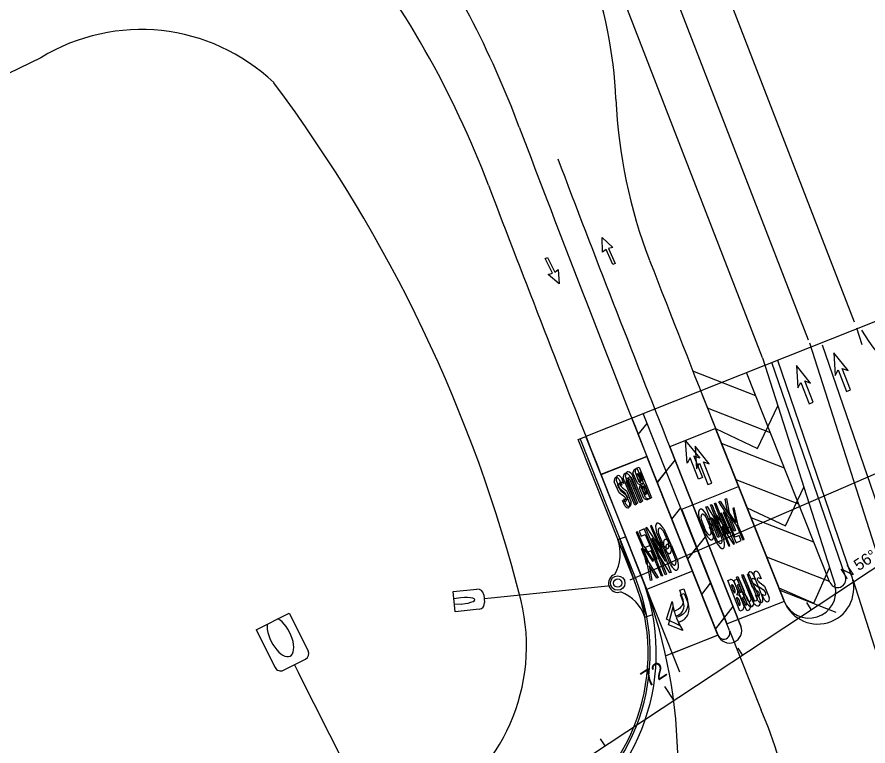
# Model space of a CAD drawing. Extents: x 468143 to 491361, y 1438528 to 1468730.
# Drawn here: x 489927.9 to 490134.6, y 1467030.2 to 1467207.3 of the extents above; entities that cross this region are included whole.
import ezdxf

# ---------------------------------------------------------------- set-up
doc = ezdxf.new("R2010")
doc.units = 0
doc.layers.add('Default', color=7, linetype='Continuous')
doc.layers.add('Xreference_dp', color=7, linetype='Continuous')

# ---------------------------------------------------------------- blocks, each defined once
blk = doc.blocks.new('POINT_DISPLAY')
at = {"layer": 'Default'}
blk.add_line((0, 0), (0, 0), dxfattribs=at)
blk = doc.blocks.new('InltCurb2_35')
at = {"layer": 'Default'}
for p, q in [((-10, 2), (-10, 0)), ((-10, 1.5), (10, 1.5)), ((10, 2), (10, 0))]:
    blk.add_line(p, q, dxfattribs=at)
for radius in [1.75, 1]:
    blk.add_circle((0, 5.5), radius, dxfattribs=at)
for centre, radius, start, end in [((0, 5.5), 2.25, 0, 180), ((-9.85, 12), 10, 269.1432, 319.4677), ((9.85, 12), 10, 220.5323, 270.8568)]:
    blk.add_arc(centre, radius, start, end, dxfattribs=at)
for p in [(-1.6, 6.2), (-1.22, 6.76), (-0.66, 7.12), (0, 7.75), (0, 7.25), (0, 7.25), (0.7, 7.1), (1.26, 6.72), (-1.75, 5.5), (-1.75, 5.5), (-1.62, 4.84), (-1.26, 4.28), (0, 5.5), (0, 5.5), (1.22, 4.24), (1.6, 4.8), (1.62, 6.16), (1.75, 5.5), (1.75, 5.5), (-0.7, 3.9), (0, 3.75), (0, 3.75), (0.66, 3.88), (0, 0), (0, 0)]:
    blk.add_blockref('POINT_DISPLAY', p, dxfattribs=at)
blk = doc.blocks.new('MESC18RCP4S')
at = {"layer": 'Default'}
for p, q in [((-0.96, 2.29), (0.96, 2.29)), ((0, 2.29), (0, 3.97)), ((-2.46, -5.03), (-2.46, 0.79)), ((2.46, 0.79), (2.46, -5.03)), ((-0.75, -3.28), (-0.71, -5.03)), ((0.75, -3.28), (0.7, -5.03)), ((2.46, -5.03), (-2.46, -5.03))]:
    blk.add_line(p, q, dxfattribs=at)
for centre, start, end in [((-0.96, 0.79), 90, 180), ((0.96, 0.79), 0, 90)]:
    blk.add_arc(centre, 1.5, start, end, dxfattribs=at)
blk.add_ellipse((0, -3), major_axis=(0, 3), ratio=0.25, start_param=4.617261, end_param=7.949056, dxfattribs=at)
for p in [(0, 3.97), (0, 2.29), (0, 0), (0, 0), (0, -5.03)]:
    blk.add_blockref('POINT_DISPLAY', p, dxfattribs=at)
blk = doc.blocks.new('MESC60RCP2S')
at = {"layer": 'Default'}
for p, q in [((0, 2.34), (0, 4.55)), ((3, 2.34), (-3, 2.34)), ((-4.5, -9.45), (-4.5, 0.84)), ((4.5, -9.45), (4.5, 0.84)), ((4.5, -9.45), (-4.5, -9.45))]:
    blk.add_line(p, q, dxfattribs=at)
for centre, start, end in [((-3, 0.84), 90, 180), ((3, 0.84), 0, 90)]:
    blk.add_arc(centre, 1.5, start, end, dxfattribs=at)
blk.add_ellipse((0, -5.22), major_axis=(0, -5.22), ratio=0.478691, start_param=0.629157, end_param=5.654028, dxfattribs=at)
for p in [(0, 4.55), (0, 2.34), (0, 0), (0, 0), (0, -9.45)]:
    blk.add_blockref('POINT_DISPLAY', p, dxfattribs=at)
blk = doc.blocks.new('DARightTurn')
at = {"layer": 'Default'}
for points in [[(2, 2.17), (0, 2.17), (0, 3.17), (2.67, 3.17)], [(5.67, -3.17), (2, -0.5), (4.33, -0.83), (4.33, -0.17)], [(6, -0.17), (6, -0.83), (8.25, -0.5), (5.67, -3.17)]]:
    blk.add_lwpolyline(points, dxfattribs=at)
for centre, radius in [((2, -0.17), 2.33), ((2.67, -0.17), 3.33)]:
    blk.add_arc(centre, radius, 360, 90, dxfattribs=at)
blk = doc.blocks.new('ONLY_5')
at = {"layer": 'Default'}
for p, q in [((1.94, 3.96), (6.06, 3.96)), ((5.6, 3.63), (2.4, 3.63)), ((2.4, 2.29), (5.6, 2.29)), ((6.06, 1.96), (1.94, 1.96))]:
    blk.add_line(p, q, dxfattribs=at)
for points in [[(0, -0.12), (0, 0.21), (5, 1.13), (0, 1.13), (0, 1.46), (8, 1.46), (8, 1.13), (2.9, 0.21), (8, 0.21), (8, -0.12), (0, -0.12)], [(1.33, -2.12), (0, -2.12), (0, -0.79), (8, -0.79), (8, -1.12), (1.33, -1.12), (1.33, -2.12)], [(8, -3.96), (3.67, -3.12), (0, -3.12), (0, -2.79), (3.67, -2.79), (8, -1.96), (8, -2.3), (4.57, -2.96), (8, -3.62), (8, -3.96)]]:
    blk.add_lwpolyline(points, dxfattribs=at)
for major_axis, ratio, start_param, end_param in [((4, 0), 0.291667, 2.111896, 4.171289), ((2.67, 0), 0.3125, 2.214297, 4.068888), ((2.67, 0), 0.3125, 5.35589, 7.210481), ((4, 0), 0.291667, 5.253489, 7.312882)]:
    blk.add_ellipse((4, 2.96), major_axis=major_axis, ratio=ratio, start_param=start_param, end_param=end_param, dxfattribs=at)
blk = doc.blocks.new('BUS_6')
at = {"layer": 'Default'}
for p, q in [((0, 2.46), (0, 3.17)), ((0, 3.17), (8, 3.17)), ((3.33, 2.83), (1.33, 2.83)), ((1.33, 2.83), (1.33, 2.58)), ((3.33, 2.58), (3.33, 2.83)), ((6.67, 2.83), (4.67, 2.83)), ((4.67, 2.83), (4.67, 2.58)), ((6.67, 2.58), (6.67, 2.83)), ((8, 3.17), (8, 2.46)), ((3.38, 1.83), (0.62, 1.83)), ((0.97, 0.86), (8, 0.86)), ((8, 0.5), (2, 0.5)), ((7.38, 1.83), (4.62, 1.83)), ((8, 0.86), (8, 0.5)), ((0.8, -1.83), (2.26, -1.83)), ((8, -0.83), (0.89, -0.83)), ((2, -0.5), (8, -0.5)), ((3.08, -2.5), (4.23, -1.83)), ((4.23, -1.83), (7.2, -1.83)), ((8, -0.5), (8, -0.83)), ((3.77, -3.17), (0.8, -3.17)), ((4.93, -2.5), (3.77, -3.17)), ((7.2, -3.17), (5.74, -3.17))]:
    blk.add_line(p, q, dxfattribs=at)
for centre, major_axis, ratio, start_param, end_param in [((2, 2.83), (-2.08, 0), 0.64, 0.283794, 0.848062), ((2.33, 2.83), (-1.17, 0), 0.428571, 0.5411, 2.600493), ((2, 2.83), (-2.08, 0), 0.64, 2.293531, 2.857799), ((6, 2.83), (2.08, 0), 0.64, 3.425387, 3.989655), ((5.67, 2.83), (1.17, 0), 0.428571, 3.682692, 5.742086), ((6, 2.83), (2.08, 0), 0.64, 5.435123, 5.999391), ((2, 0), (2, 0), 0.5, 2.110653, 4.126703), ((2, 0), (0.667, 0), 0.75, 1.570796, 4.712389), ((2, -2.5), (-2, 0), 0.416667, 5.35589, 7.210481), ((2.67, -2.17), (-0.877, -0.48), 0.5, 4.914869, 8.056461), ((6, -2.5), (2, 0), 0.416667, 5.35589, 7.210481), ((5.33, -2.83), (-0.869, -0.495), 0.5, 1.760499, 4.902092)]:
    blk.add_ellipse(centre, major_axis=major_axis, ratio=ratio, start_param=start_param, end_param=end_param, dxfattribs=at)
blk = doc.blocks.new('DAThru_1')
at = {"layer": 'Default'}
blk.add_lwpolyline([(4.58, -1.67), (5.58, -0.5), (0, -0.5), (0, 0.5), (5.58, 0.5), (4.58, 1.67), (9.83, 0), (4.58, -1.67)], dxfattribs=at)
blk = doc.blocks.new('DAMerge')
at = {"layer": 'Default'}
blk.add_lwpolyline([(0.71, -4.09), (4.66, -0.15), (4.77, -1.68), (7.31, 3.21), (2.42, 0.68), (3.95, 0.56), (0, -3.39), (0.71, -4.09)], dxfattribs=at)
blk = doc.blocks.new('DALeftTurn_4')
at = {"layer": 'Default'}
for points in [[(5.67, 3.17), (2, 0.5), (4.33, 0.83), (4.33, 0.17)], [(6, 0.17), (6, 0.83), (8.25, 0.5), (5.67, 3.17)], [(2, -2.17), (0, -2.17), (0, -3.17), (2.67, -3.17)]]:
    blk.add_lwpolyline(points, dxfattribs=at)
for centre, radius in [((2, 0.17), 2.33), ((2.67, 0.17), 3.33)]:
    blk.add_arc(centre, radius, 270, 0, dxfattribs=at)
blk = doc.blocks.new('BikeONLY')
at = {"layer": 'Default'}
for p, q in [((0.97, 1.83), (3.03, 1.83)), ((2.8, 1.67), (1.2, 1.67)), ((3.03, 0.83), (0.97, 0.83)), ((1.2, 1), (2.8, 1))]:
    blk.add_line(p, q, dxfattribs=at)
for points in [[(0, -0.17), (4, -0.17), (4, 0), (1.45, 0), (4, 0.46), (4, 0.62), (0, 0.62), (0, 0.46), (2.5, 0.46), (0, 0), (0, -0.17)], [(0, -1.04), (0.67, -1.04), (0.67, -0.54), (4, -0.54), (4, -0.37), (0, -0.37), (0, -1.04)], [(4, -1.83), (4, -1.66), (2.28, -1.33), (4, -1), (4, -0.83), (1.83, -1.25), (0, -1.25), (0, -1.42), (1.83, -1.42), (4, -1.83)]]:
    blk.add_lwpolyline(points, dxfattribs=at)
for major_axis, ratio, start_param, end_param in [((2, 0), 0.291667, 2.111896, 4.171289), ((1.33, 0), 0.3125, 2.214297, 4.068888), ((1.33, 0), 0.3125, 5.35589, 7.210481), ((2, 0), 0.291667, 5.253489, 7.312882)]:
    blk.add_ellipse((2, 1.33), major_axis=major_axis, ratio=ratio, start_param=start_param, end_param=end_param, dxfattribs=at)
blk = doc.blocks.new('BUS')
at = {"layer": 'Default'}
for p, q in [((0, 2.46), (0, 3.17)), ((0, 3.17), (8, 3.17)), ((3.33, 2.83), (1.33, 2.83)), ((1.33, 2.83), (1.33, 2.58)), ((3.33, 2.58), (3.33, 2.83)), ((6.67, 2.83), (4.67, 2.83)), ((4.67, 2.83), (4.67, 2.58)), ((6.67, 2.58), (6.67, 2.83)), ((8, 3.17), (8, 2.46)), ((3.38, 1.83), (0.62, 1.83)), ((0.97, 0.86), (8, 0.86)), ((8, 0.5), (2, 0.5)), ((7.38, 1.83), (4.62, 1.83)), ((8, 0.86), (8, 0.5)), ((0.8, -1.83), (2.26, -1.83)), ((8, -0.83), (0.89, -0.83)), ((2, -0.5), (8, -0.5)), ((3.08, -2.5), (4.23, -1.83)), ((4.23, -1.83), (7.2, -1.83)), ((8, -0.5), (8, -0.83)), ((3.77, -3.17), (0.8, -3.17)), ((4.93, -2.5), (3.77, -3.17)), ((7.2, -3.17), (5.74, -3.17))]:
    blk.add_line(p, q, dxfattribs=at)
for centre, major_axis, ratio, start_param, end_param in [((2, 2.83), (-2.08, 0), 0.64, 0.283794, 0.848062), ((2.33, 2.83), (-1.17, 0), 0.428571, 0.5411, 2.600493), ((2, 2.83), (-2.08, 0), 0.64, 2.293531, 2.857799), ((6, 2.83), (2.08, 0), 0.64, 3.425387, 3.989655), ((5.67, 2.83), (1.17, 0), 0.428571, 3.682692, 5.742086), ((6, 2.83), (2.08, 0), 0.64, 5.435123, 5.999391), ((2, 0), (2, 0), 0.5, 2.110653, 4.126703), ((2, 0), (0.667, 0), 0.75, 1.570796, 4.712389), ((2, -2.5), (-2, 0), 0.416667, 5.35589, 7.210481), ((2.67, -2.17), (-0.877, -0.48), 0.5, 4.914869, 8.056461), ((6, -2.5), (2, 0), 0.416667, 5.35589, 7.210481), ((5.33, -2.83), (-0.869, -0.495), 0.5, 1.760499, 4.902092)]:
    blk.add_ellipse(centre, major_axis=major_axis, ratio=ratio, start_param=start_param, end_param=end_param, dxfattribs=at)

msp = doc.modelspace()

# ---------------------------------------------------------------- linework, layer by layer
at = {"layer": 'Xreference_dp'}
for p, q in [((490131.32, 1467133.11), (490088.77, 1467243.04)), ((490131.32, 1467133.11), (490088.77, 1467243.04)), ((490120.13, 1467128.78), (490077.58, 1467238.71)), ((490120.13, 1467128.78), (490077.58, 1467238.71)), ((490108.94, 1467124.45), (490066.39, 1467234.38)), ((490108.94, 1467124.45), (490066.39, 1467234.38)), ((489933.74, 1467197.39), (489863.69, 1467163.48)), ((489933.74, 1467197.39), (489863.69, 1467163.48)), ((490051.34, 1467017.44), (490235.32, 1467139.02)), ((490136.39, 1467133.34), (490066.06, 1467105.41)), ((490131.8, 1467131.76), (490133.08, 1467127.75)), ((490131.8, 1467131.76), (490133.08, 1467127.75)), ((490120.37, 1467128.1), (490138, 1467072.93)), ((490120.37, 1467128.1), (490138, 1467072.93)), ((490141.39, 1467075.55), (490123.54, 1467127.57)), ((490108.94, 1467124.45), (490126.57, 1467069.27)), ((490108.94, 1467124.45), (490126.57, 1467069.27)), ((490129.09, 1467071.33), (490111.24, 1467123.35)), ((490130.51, 1467071.81), (490112.66, 1467123.84)), ((490107.33, 1467115.29), (490092.06, 1467121.24)), ((490125.34, 1467069.94), (490105.1, 1467120.91)), ((490114.19, 1467065.51), (490093.95, 1467116.48)), ((490172.03, 1467111.76), (490076.72, 1467070.5)), ((490100.95, 1467058.21), (490080.01, 1467110.94)), ((490110.9, 1467106.29), (490095.63, 1467112.24)), ((490098.16, 1467057.1), (490077.22, 1467109.84)), ((490078.81, 1467105.82), (490080.96, 1467108.54)), ((490114.25, 1467065.34), (490097.59, 1467107.29)), ((490114.25, 1467065.34), (490097.59, 1467107.29)), ((490064.21, 1467104.67), (490066.06, 1467105.41)), ((490077.8, 1467070.45), (490064.21, 1467104.67)), ((490078.26, 1467070.64), (490064.67, 1467104.85)), ((490079.65, 1467071.19), (490066.06, 1467105.41)), ((490079.56, 1467071.42), (490066.06, 1467105.41)), ((490103.73, 1467059.31), (490086.43, 1467102.86)), ((490103.73, 1467059.31), (490086.43, 1467102.86)), ((490114.31, 1467097.71), (490099.04, 1467103.66)), ((490098.15, 1467057.1), (490080.89, 1467100.55)), ((490098.15, 1467057.1), (490080.89, 1467100.55)), ((490083.42, 1467094.18), (490087.72, 1467099.61)), ((490083.42, 1467094.18), (490087.72, 1467099.61)), ((490083.44, 1467094.18), (490085.59, 1467096.89)), ((490117.81, 1467088.9), (490102.54, 1467094.85)), ((490086.95, 1467085.32), (490089.1, 1467088.04)), ((490121.46, 1467079.7), (490106.19, 1467085.65)), ((490090.81, 1467075.59), (490095.1, 1467081.02)), ((490090.81, 1467075.59), (490095.1, 1467081.02)), ((490090.82, 1467075.59), (490092.97, 1467078.31)), ((490125.27, 1467070.11), (490110, 1467076.06)), ((490094.22, 1467067.02), (490096.37, 1467069.73)), ((490130.87, 1467070.64), (490142.34, 1467034.75)), ((490043.04, 1467066.17), (490072.16, 1467069.19)), ((490126.85, 1467062.65), (490113.22, 1467067.96)), ((490097.55, 1467058.61), (490101.85, 1467064.05)), ((490097.55, 1467058.61), (490101.85, 1467064.05)), ((490120.81, 1467063.35), (490119.71, 1467065.02)), ((490097.56, 1467058.61), (490099.71, 1467061.33)), ((490098.16, 1467057.1), (490085.49, 1467052.07)), ((490098.15, 1467057.1), (490087, 1467052.67)), ((490098.15, 1467057.1), (490087, 1467052.67)), ((490100.95, 1467058.21), (490108.61, 1467038.92)), ((490104.13, 1467052.32), (490103.02, 1467053.99)), ((490021.16, 1466998.87), (489996.32, 1467047.97)), ((490087.44, 1467041.3), (490085.24, 1467044.63)), ((490070.76, 1467030.27), (490069.65, 1467031.94))]:
    msp.add_line(p, q, dxfattribs=at)
for points in [[(490073.21, 1467147.43), (490072.64, 1467147.18), (490071.03, 1467150.77), (490070.14, 1467150.16), (490070.06, 1467153.69), (490072.64, 1467151.29), (490071.6, 1467151.02)], [(490073.21, 1467147.43), (490072.64, 1467147.18), (490071.03, 1467150.77), (490070.14, 1467150.16), (490070.06, 1467153.69), (490072.64, 1467151.29), (490071.6, 1467151.02)], [(490056.21, 1467148.59), (490056.77, 1467148.87), (490058.51, 1467145.33), (490059.38, 1467145.97), (490059.58, 1467142.44), (490056.91, 1467144.76), (490057.95, 1467145.06)], [(490056.21, 1467148.59), (490056.77, 1467148.87), (490058.51, 1467145.33), (490059.38, 1467145.97), (490059.58, 1467142.44), (490056.91, 1467144.76), (490057.95, 1467145.06)], [(490091.98, 1467072.67), (490080.83, 1467068.24), (490069.75, 1467096.12), (490080.9, 1467100.55)], [(490089.34, 1467087.72), (490103.16, 1467093.21), (490114.24, 1467065.33), (490100.42, 1467059.84)]]:
    msp.add_lwpolyline(points, close=True, dxfattribs=at)
for points in [[(490097.59, 1467107.29), (490107.78, 1467102.47), (490112.66, 1467112.79)], [(490097.59, 1467107.29), (490107.78, 1467102.47), (490112.66, 1467112.79)], [(490114.25, 1467065.34), (490097.59, 1467107.29), (490086.43, 1467102.86), (490103.73, 1467059.31)], [(490114.25, 1467065.34), (490097.59, 1467107.29), (490086.43, 1467102.86), (490103.73, 1467059.31)], [(490069.74, 1467096.12), (490080.89, 1467100.55)], [(490098.15, 1467057.1), (490080.89, 1467100.55), (490069.74, 1467096.12), (490088.77, 1467048.22)], [(490069.74, 1467096.12), (490080.89, 1467100.55)], [(490098.15, 1467057.1), (490080.89, 1467100.55), (490069.74, 1467096.12), (490088.77, 1467048.22)], [(490105.23, 1467088.03), (490114.53, 1467083.64), (490118.97, 1467093.05)], [(490105.23, 1467088.03), (490114.53, 1467083.64), (490118.97, 1467093.05)], [(490112.95, 1467068.59), (490121.39, 1467064.85), (490125.22, 1467073.49)], [(490112.95, 1467068.59), (490121.39, 1467064.85), (490125.22, 1467073.49)]]:
    msp.add_lwpolyline(points, dxfattribs=at)
for centre, radius, start, end in [((489815.1, 1467091.86), 251, 20.6873, 34.1721), ((489815.1, 1467091.86), 251, 20.6873, 34.1721), ((489819.23, 1467081.59), 238.77, 20.8069, 38.2362), ((489819.23, 1467081.59), 238.77, 20.8069, 38.2362), ((489965.55, 1467182.73), 107.92, 2.4412, 20.3736), ((489965.55, 1467182.73), 107.92, 2.4412, 20.3736), ((489958.06, 1467157.57), 46.66, 46.3453, 121.4133), ((489958.06, 1467157.57), 46.66, 46.3453, 121.4133), ((489704.3, 1466977.51), 357.06, 14.2565, 36.7851), ((489704.3, 1466977.51), 357.06, 14.2565, 36.7851), ((490196.26, 1467192.57), 123, 182.4412, 201.1596), ((490196.26, 1467192.57), 123, 182.4412, 201.1596), ((494770.62, 1468963.13), 5046.06, 200.68725, 201.66109), ((494770.62, 1468963.13), 5046.06, 200.68725, 201.66109), ((494770.62, 1468963.13), 5040.06, 200.80691, 201.66109), ((494770.62, 1468963.13), 5040.06, 200.80691, 201.66109), ((494770.62, 1468963.13), 5058.06, 200.80691, 201.66109), ((494770.62, 1468963.13), 5058.06, 200.80691, 201.66109), ((494770.62, 1468963.13), 5028.06, 201.15959, 201.66109), ((494770.62, 1468963.13), 5028.06, 201.15959, 201.66109), ((490187.33, 1467165.03), 64, 211.8829, 306.1516), ((489962.81, 1467025.06), 125.62, 1.5824, 21.6611), ((490122.37, 1467068.57), 8.76, 201.7396, 21.7273), ((490127.2, 1467070.68), 2, 201.6611, 18.9385), ((490033.18, 1467052.73), 48, 299.99, 21.6611), ((490033.18, 1467052.73), 48.5, 299.99, 21.6611), ((490033.18, 1467052.73), 50, 299.99, 21.6611), ((490120.27, 1467067.73), 6.48, 201.6611, 13.7826), ((490120.27, 1467067.73), 6.48, 201.6611, 13.7826), ((490004.74, 1467054.47), 46.92, 299.021, 13.5238), ((490004.74, 1467054.47), 46.92, 299.021, 13.5238), ((489145.02, 1468591.69), 1909.86, 245.36712, 306.9274), ((490100.94, 1467058.21), 3, 201.6611, 21.6611), ((490100.94, 1467058.21), 3, 201.6611, 21.6611), ((490099.56, 1467057.64), 1.5, 201.1413, 22.1809), ((490023.78, 1467000.79), 93, 296.0457, 24.205), ((490037.59, 1467002.13), 109.71, 299.595, 17.295)]:
    msp.add_arc(centre, radius, start, end, dxfattribs=at)

# ---------------------------------------------------------------- block references
for name, p, rotation in [('DAMerge', (490126.28, 1467117.7), 66.4110902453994), ('DAMerge', (490126.28, 1467117.7), 66.4110902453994), ('DAMerge', (490117.21, 1467114.67), 66.4110902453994), ('DAMerge', (490117.21, 1467114.67), 66.4110902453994), ('DAThru_1', (490093.92, 1467095.22), 111.66109415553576), ('DAMerge', (490092.6, 1467095.03), 66.4110902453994), ('DAMerge', (490092.6, 1467095.03), 66.4110902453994), ('BUS', (490075.56, 1467096.39), -66.60299127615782), ('BUS', (490075.56, 1467096.39), -66.60299127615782), ('BUS_6', (490076.1, 1467096.77), -68.33890584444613), ('ONLY_5', (490099.5, 1467081.38), 111.66109415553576), ('InltCurb2_35', (490079.01, 1467071.57), 109.16992064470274), ('ONLY_5', (490082.49, 1467079.26), -68.33890584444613), ('BUS_6', (490106.42, 1467064.11), 111.66109415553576), ('BUS', (490108.03, 1467064.28), 113.3970087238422), ('BUS', (490108.03, 1467064.28), 113.3970087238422), ('MESC18RCP4S', (490039.09, 1467065.76), -84.07722676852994), ('DARightTurn', (490087.01, 1467066.08), -68.33890584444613), ('MESC60RCP2S', (489994.26, 1467052.03), -153.12726008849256)]:
    msp.add_blockref(name, p, dxfattribs=dict(at, rotation=rotation))
at = {"layer": 'Xreference_dp', "yscale": 2.0000000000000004}
for p, xscale, rotation in [((490101.89, 1467079.25), 2.000000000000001, 113.3970087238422), ((490101.89, 1467079.25), 2.000000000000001, 113.3970087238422), ((490080.9, 1467083.24), 2.0000000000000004, -66.60299127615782), ((490080.9, 1467083.24), 2.0000000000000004, -66.60299127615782)]:
    msp.add_blockref('BikeONLY', p, dxfattribs=dict(at, xscale=xscale, rotation=rotation))
at = {"layer": 'Xreference_dp', "yscale": -1, "rotation": -71.71816976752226}
msp.add_blockref('DALeftTurn_4', (490086.87, 1467067.35), dxfattribs=at)
msp.add_blockref('DALeftTurn_4', (490086.87, 1467067.35), dxfattribs=at)

# ---------------------------------------------------------------- texts
at = {"layer": 'Xreference_dp'}
for s, height, p in [('N 56%%d 32\' 31" E', 2.8, (490129.18, 1467070.56)), ('72', 4, (490081.14, 1467044.32))]:
    msp.add_text(s, height=height, rotation=33.458, dxfattribs=at).set_placement(p)

doc.saveas('drawing.dxf')
